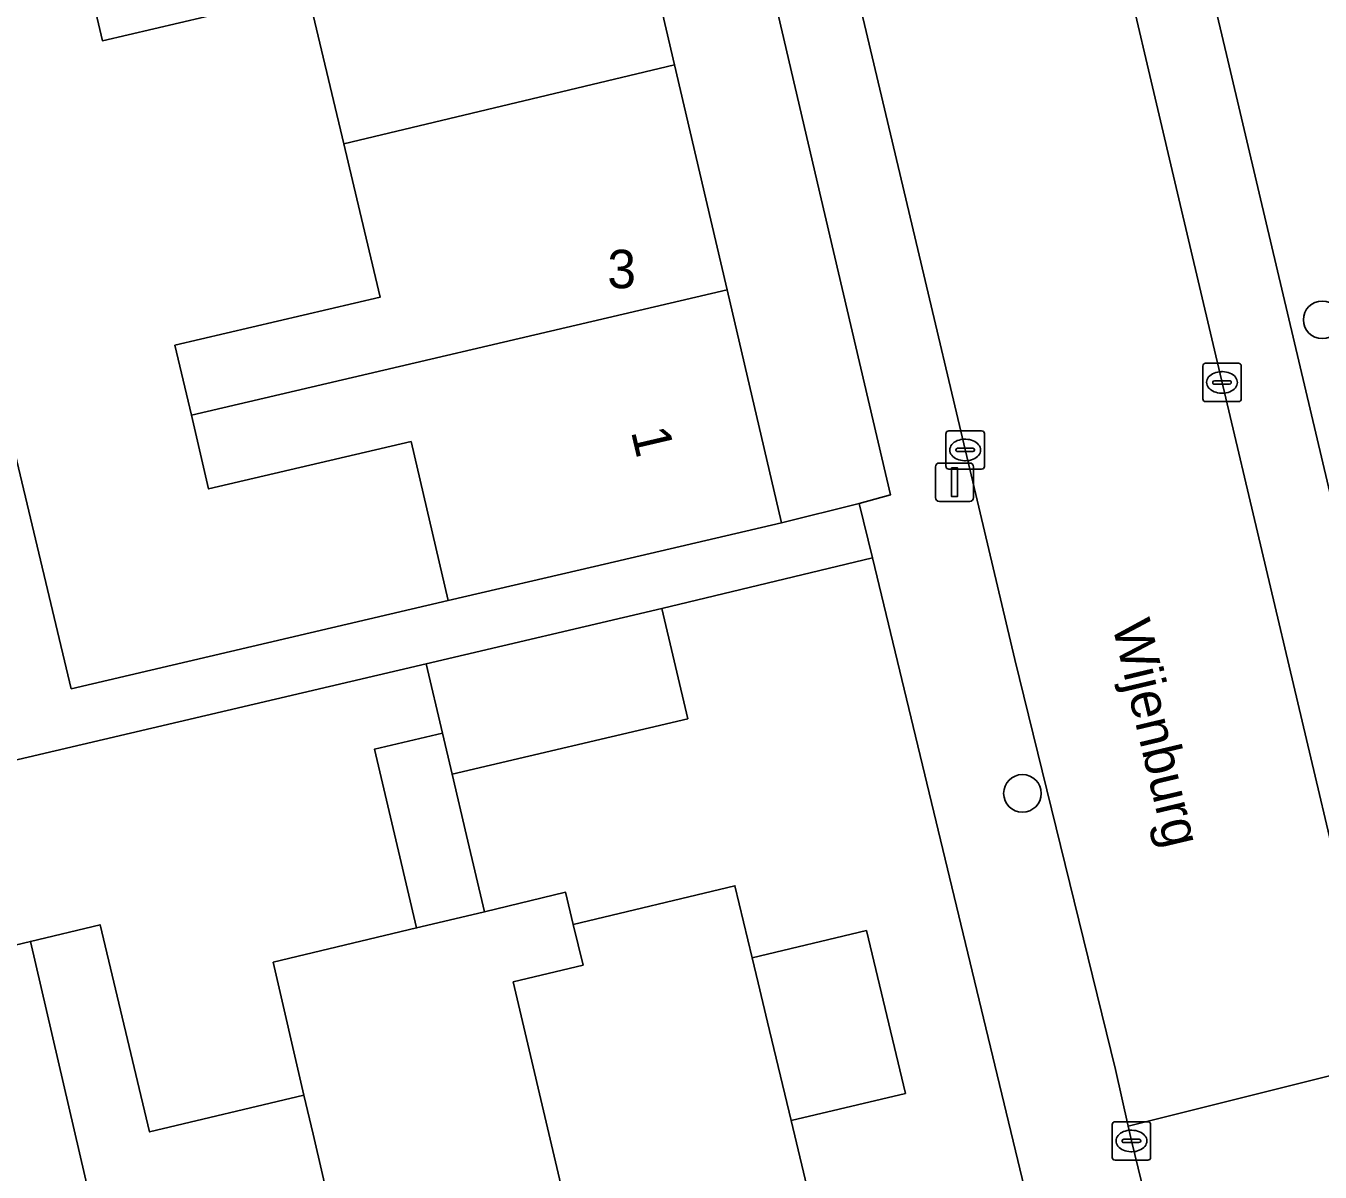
# Model space of a CAD drawing. Extents: x 158031 to 159244, y 380104 to 381214.
# Drawn here: x 158590.29 to 158623.97, y 380724.66 to 380754.5 of the extents above; entities that cross this region are included whole.
import ezdxf

# ---------------------------------------------------------------- set-up
doc = ezdxf.new("R2010")
doc.units = 0
for name, color, linetype in [('IMGEO_Boom', 7, 'Continuous'), ('IMGEO_Erf', 7, 'Continuous'), ('IMGEO_Kolk', 7, 'Continuous'), ('IMGEO_Lichtmast', 7, 'Continuous'), ('IMGEO_Openbare_ruimte_label', 7, 'Continuous'), ('IMGEO_Pand', 7, 'Continuous'), ('IMGEO_Pand_nummerreeks', 7, 'Continuous'), ('IMGEO_Parkeervlak_open', 7, 'Continuous'), ('IMGEO_Rijbaan_lokaal_gesloten', 7, 'Continuous'), ('IMGEO_Rijbaan_lokaal_open', 7, 'Continuous'), ('IMGEO_Voetpad_open', 7, 'Continuous')]:
    doc.layers.add(name, color=color, linetype=linetype)

msp = doc.modelspace()

# ---------------------------------------------------------------- linework, layer by layer
at = {"layer": 'IMGEO_Boom'}
for centre in [(158624.026, 380746.851), (158616.223, 380734.523)]:
    msp.add_circle(centre, 0.489, dxfattribs=at)
at = {"layer": 'IMGEO_Erf'}
for points in [[(158604.491, 380777.798), (158597.408, 380776.13), (158598.809, 380770.25), (158603.015, 380771.233), (158604.431, 380765.183), (158605.801, 380759.324), (158607.166, 380753.49), (158607.983, 380750), (158608.538, 380747.627), (158609.955, 380741.569), (158611.977, 380742.07), (158612.789, 380742.296), (158610.988, 380750)], [(158598.899, 380750), (158598.561, 380751.427), (158597.627, 380755.367), (158592.275, 380754.116), (158591.833, 380756.006), (158591.411, 380757.814), (158596.728, 380759.056), (158595.788, 380763.076), (158594.324, 380762.734), (158593.901, 380764.544), (158592.892, 380768.863), (158590.165, 380768.213), (158587.286, 380767.526), (158584.406, 380766.84), (158586.112, 380759.687), (158591.465, 380737.246), (158601.276, 380739.54), (158600.309, 380743.68), (158595.041, 380742.448), (158594.593, 380744.364), (158594.166, 380746.188), (158599.506, 380747.436)]]:
    msp.add_lwpolyline(points, close=True, dxfattribs=at)
for points in [[(158617.16, 380720.572), (158612.318, 380740.656), (158606.84, 380739.335), (158607.513, 380736.466), (158601.378, 380735.027), (158601.753, 380733.429), (158602.218, 380731.442), (158604.333, 380731.948), (158604.533, 380731.113), (158608.741, 380732.119), (158609.189, 380730.243), (158612.163, 380730.953), (158613.176, 380726.715), (158610.202, 380726.004), (158611.444, 380720.808)], [(158588.547, 380730.227), (158590.405, 380730.671), (158592.215, 380731.104), (158593.505, 380725.71), (158597.522, 380726.67), (158596.722, 380730.128), (158600.454, 380731.021), (158599.987, 380733.015), (158599.363, 380735.675), (158601.129, 380736.089), (158600.705, 380737.896), (158568.508, 380730.343), (158573.761, 380708.16), (158615.556, 380718.152)]]:
    msp.add_lwpolyline(points, dxfattribs=at)
at = {"layer": 'IMGEO_Kolk'}
for p, q in [((158620.917, 380744.795), (158620.917, 380745.647)), ((158620.992, 380745.721), (158621.844, 380745.721)), ((158621.405, 380745.501), (158621.43, 380745.501)), ((158621.918, 380745.647), (158621.918, 380744.795)), ((158621.176, 380745.215), (158621.176, 380745.227)), ((158621.614, 380745.178), (158621.216, 380745.178)), ((158621.219, 380745.264), (158621.617, 380745.264)), ((158621.66, 380745.227), (158621.66, 380745.215)), ((158621.428, 380744.941), (158621.403, 380744.941)), ((158621.844, 380744.721), (158620.992, 380744.721)), ((158614.233, 380743.036), (158614.233, 380743.888)), ((158614.308, 380743.962), (158615.16, 380743.962)), ((158615.234, 380743.888), (158615.234, 380743.036)), ((158614.535, 380743.505), (158614.933, 380743.505)), ((158614.721, 380743.742), (158614.746, 380743.742)), ((158614.492, 380743.456), (158614.492, 380743.468)), ((158614.93, 380743.419), (158614.532, 380743.419)), ((158614.744, 380743.182), (158614.719, 380743.182)), ((158614.976, 380743.468), (158614.976, 380743.456)), ((158615.16, 380742.962), (158614.308, 380742.962)), ((158618.634, 380725.975), (158619.486, 380725.975)), ((158618.559, 380725.049), (158618.559, 380725.901)), ((158619.047, 380725.755), (158619.072, 380725.755)), ((158619.56, 380725.901), (158619.56, 380725.049)), ((158618.818, 380725.469), (158618.818, 380725.481)), ((158619.256, 380725.432), (158618.858, 380725.432)), ((158618.861, 380725.518), (158619.259, 380725.518)), ((158619.302, 380725.481), (158619.302, 380725.469)), ((158619.486, 380724.975), (158618.634, 380724.975)), ((158619.07, 380725.195), (158619.045, 380725.195))]:
    msp.add_line(p, q, dxfattribs=at)
for points in [[(158620.917, 380744.795), (158620.917, 380745.647)], [(158620.992, 380745.721), (158621.844, 380745.721)], [(158621.918, 380745.647), (158621.918, 380744.795)], [(158621.844, 380744.721), (158620.992, 380744.721)], [(158614.233, 380743.036), (158614.233, 380743.888)], [(158614.308, 380743.962), (158615.16, 380743.962)], [(158615.234, 380743.888), (158615.234, 380743.036)], [(158615.16, 380742.962), (158614.308, 380742.962)], [(158618.634, 380725.975), (158619.486, 380725.975)], [(158618.559, 380725.049), (158618.559, 380725.901)], [(158619.56, 380725.901), (158619.56, 380725.049)], [(158619.486, 380724.975), (158618.634, 380724.975)]]:
    msp.add_lwpolyline(points, dxfattribs=at)
for centre, radius, start, end in [((158620.994, 380745.645), 0.0765, 91.552, 178.448), ((158620.994, 380745.645), 0.0765, 91.552, 178.448), ((158621.842, 380745.645), 0.0765, 1.552, 88.448), ((158621.842, 380745.645), 0.0765, 1.552, 88.448), ((158621.216, 380745.224), 0.0403, 85.8775, 175.7526), ((158621.213, 380745.214), 0.0366, 178.938, 274.7102), ((158621.617, 380745.221), 0.043, 264.8664, 352.4533), ((158621.621, 380745.226), 0.0386, 1.7309, 96.639), ((158620.994, 380744.797), 0.0765, 181.552, 268.448), ((158620.994, 380744.797), 0.0765, 181.552, 268.448), ((158621.842, 380744.797), 0.0765, 271.552, 358.448), ((158621.842, 380744.797), 0.0765, 271.552, 358.448), ((158614.31, 380743.886), 0.0765, 91.552, 178.448), ((158614.31, 380743.886), 0.0765, 91.552, 178.448), ((158615.158, 380743.886), 0.0765, 1.552, 88.448), ((158615.158, 380743.886), 0.0765, 1.552, 88.448), ((158614.532, 380743.465), 0.0403, 85.8775, 175.7526), ((158614.937, 380743.467), 0.0386, 1.7309, 96.639), ((158614.529, 380743.455), 0.0366, 178.938, 274.7102), ((158614.933, 380743.462), 0.043, 264.8664, 352.4533), ((158614.31, 380743.038), 0.0765, 181.552, 268.448), ((158614.31, 380743.038), 0.0765, 181.552, 268.448), ((158615.158, 380743.038), 0.0765, 271.552, 358.448), ((158615.158, 380743.038), 0.0765, 271.552, 358.448), ((158618.636, 380725.899), 0.0765, 91.552, 178.448), ((158618.636, 380725.899), 0.0765, 91.552, 178.448), ((158619.484, 380725.899), 0.0765, 1.552, 88.448), ((158619.484, 380725.899), 0.0765, 1.552, 88.448), ((158618.858, 380725.478), 0.0403, 85.8775, 175.7526), ((158618.855, 380725.468), 0.0366, 178.938, 274.7102), ((158619.259, 380725.475), 0.043, 264.8664, 352.4533), ((158619.263, 380725.48), 0.0386, 1.7309, 96.639), ((158618.636, 380725.051), 0.0765, 181.552, 268.448), ((158618.636, 380725.051), 0.0765, 181.552, 268.448), ((158619.484, 380725.051), 0.0765, 271.552, 358.448), ((158619.484, 380725.051), 0.0765, 271.552, 358.448)]:
    msp.add_arc(centre, radius, start, end, dxfattribs=at)
for centre, major_axis, ratio, start_param, end_param in [((158621.404, 380745.221), (-0.387, 0.002), 0.722429, 4.712389, 7.853982), ((158621.429, 380745.221), (-0.39, 0.002), 0.717154, 1.570796, 4.712389), ((158614.72, 380743.462), (-0.387, 0.002), 0.722429, 4.712389, 7.853982), ((158614.745, 380743.462), (-0.39, 0.002), 0.717154, 1.570796, 4.712389), ((158619.046, 380725.475), (-0.387, 0.002), 0.722429, 4.712389, 7.853982), ((158619.071, 380725.475), (-0.39, 0.002), 0.717154, 1.570796, 4.712389)]:
    msp.add_ellipse(centre, major_axis=major_axis, ratio=ratio, start_param=start_param, end_param=end_param, dxfattribs=at)
at = {"layer": 'IMGEO_Lichtmast'}
for p, q in [((158613.96, 380742.223), (158613.96, 380743.023)), ((158613.96, 380743.023), (158613.96, 380742.223)), ((158614.06, 380743.123), (158614.85, 380743.123)), ((158614.85, 380743.123), (158614.06, 380743.123)), ((158614.95, 380743.023), (158614.95, 380742.223)), ((158614.95, 380742.223), (158614.95, 380743.023)), ((158614.85, 380742.123), (158614.06, 380742.123)), ((158614.06, 380742.123), (158614.85, 380742.123))]:
    msp.add_line(p, q, dxfattribs=at)
msp.add_lwpolyline([(158614.38, 380742.998), (158614.53, 380742.998), (158614.53, 380742.248), (158614.38, 380742.248), (158614.38, 380742.998)], dxfattribs=at)
for centre, start, end in [((158614.06, 380743.023), 90, 180), ((158614.06, 380743.023), 90, 180), ((158614.85, 380743.023), 0, 90), ((158614.85, 380743.023), 360, 90), ((158614.06, 380742.223), 180, 270), ((158614.06, 380742.223), 180, 270), ((158614.85, 380742.223), 270, 0), ((158614.85, 380742.223), 270, 0)]:
    msp.add_arc(centre, 0.1, start, end, dxfattribs=at)
at = {"layer": 'IMGEO_Pand'}
for points in [[(158598.561, 380751.427), (158607.166, 380753.49), (158605.801, 380759.324), (158591.833, 380756.006), (158592.275, 380754.116), (158597.627, 380755.367)], [(158598.561, 380751.427), (158598.899, 380750), (158599.506, 380747.436), (158594.166, 380746.188), (158594.593, 380744.364), (158608.538, 380747.627), (158607.983, 380750), (158607.166, 380753.49)], [(158608.538, 380747.627), (158594.593, 380744.364), (158595.041, 380742.448), (158600.309, 380743.68), (158601.276, 380739.54), (158605.087, 380740.431), (158609.955, 380741.569)], [(158606.84, 380739.335), (158600.705, 380737.896), (158601.129, 380736.089), (158601.378, 380735.027), (158607.513, 380736.466)], [(158601.378, 380735.027), (158601.129, 380736.089), (158599.363, 380735.675), (158599.987, 380733.015), (158600.454, 380731.021), (158600.711, 380731.082), (158602.218, 380731.442), (158601.753, 380733.429)], [(158609.189, 380730.243), (158608.741, 380732.119), (158604.533, 380731.113), (158604.786, 380730.053), (158602.972, 380729.617), (158605.379, 380719.358), (158611.444, 380720.808), (158610.202, 380726.004), (158609.589, 380728.57), (158609.345, 380729.59)], [(158602.972, 380729.617), (158604.786, 380730.053), (158604.533, 380731.113), (158604.333, 380731.948), (158602.218, 380731.442), (158600.711, 380731.082), (158600.454, 380731.021), (158596.722, 380730.128), (158597.522, 380726.67), (158597.758, 380725.65), (158599.537, 380717.961), (158605.379, 380719.358)], [(158597.522, 380726.67), (158593.505, 380725.71), (158592.215, 380731.104), (158590.405, 380730.671), (158593.675, 380716.56), (158599.537, 380717.961), (158597.758, 380725.65)], [(158609.189, 380730.243), (158609.345, 380729.59), (158609.589, 380728.57), (158610.202, 380726.004), (158613.176, 380726.715), (158612.163, 380730.953)], [(158590.405, 380730.671), (158588.547, 380730.227), (158589.833, 380724.846), (158585.83, 380723.889), (158587.833, 380715.163), (158593.675, 380716.56)]]:
    msp.add_lwpolyline(points, close=True, dxfattribs=at)
at = {"layer": 'IMGEO_Parkeervlak_open'}
msp.add_lwpolyline([(158627.774, 380727.324), (158622.417, 380750), (158621.53, 380753.756), (158620.656, 380757.457), (158615.415, 380779.644), (158613.34, 380779.174), (158616.461, 380766.319), (158620.294, 380750), (158621.401, 380745.287), (158625.599, 380727.516)], dxfattribs=at)
at = {"layer": 'IMGEO_Rijbaan_lokaal_gesloten'}
msp.add_lwpolyline([(158625.847, 380726.467), (158625.599, 380727.516), (158618.975, 380725.857), (158619.06, 380725.475), (158620.191, 380720.852), (158626.931, 380722.326), (158626.597, 380723.434)], close=True, dxfattribs=at)
at = {"layer": 'IMGEO_Rijbaan_lokaal_open'}
msp.add_lwpolyline([(158601.755, 380798.591), (158602.585, 380794.954), (158604.015, 380788.692), (158605.732, 380781.448), (158613.185, 380750), (158615.123, 380741.822), (158616.028, 380738.005), (158618.646, 380727.333), (158618.975, 380725.857), (158625.599, 380727.516), (158621.401, 380745.287), (158620.294, 380750), (158616.461, 380766.319), (158613.34, 380779.174), (158612.554, 380782.409), (158609.13, 380797.277)], dxfattribs=at)
at = {"layer": 'IMGEO_Voetpad_open'}
for points in [[(158582.927, 380865.443), (158599.515, 380795.166), (158600.252, 380792.284), (158601.053, 380788.365), (158601.167, 380787.602), (158602.537, 380781.61), (158604.491, 380777.798), (158610.988, 380750), (158612.789, 380742.296), (158611.977, 380742.07), (158612.318, 380740.656), (158617.16, 380720.572)], [(158609.13, 380797.277), (158612.554, 380782.409), (158613.34, 380779.174), (158615.415, 380779.644), (158620.656, 380757.457), (158621.53, 380753.756), (158622.417, 380750), (158627.774, 380727.324)], [(158620.191, 380720.852), (158619.06, 380725.475), (158618.975, 380725.857), (158618.646, 380727.333), (158616.028, 380738.005), (158615.123, 380741.822), (158613.185, 380750), (158605.732, 380781.448), (158604.015, 380788.692)]]:
    msp.add_lwpolyline(points, dxfattribs=at)
msp.add_lwpolyline([(158600.705, 380737.896), (158606.84, 380739.335), (158612.318, 380740.656), (158611.977, 380742.07), (158609.955, 380741.569), (158605.087, 380740.431), (158601.276, 380739.54), (158591.465, 380737.246), (158586.112, 380759.687), (158584.406, 380766.84), (158583.009, 380772.697), (158581.455, 380772.326), (158582.853, 380766.459), (158588.426, 380742.845), (158588.845, 380741.072), (158589.846, 380736.837), (158579.907, 380734.482), (158576.02, 380733.561), (158571.154, 380732.409), (158568.185, 380731.708), (158568.508, 380730.343)], close=True, dxfattribs=at)

# ---------------------------------------------------------------- texts
at = {"layer": 'IMGEO_Openbare_ruimte_label'}
msp.add_text('Wijenburg', height=1, rotation=283.3553, dxfattribs=at).set_placement((158618.553, 380738.911))
at = {"layer": 'IMGEO_Pand_nummerreeks'}
msp.add_text('3', height=1, dxfattribs=at).set_placement((158605.42, 380747.673))
msp.add_text('1', height=1, rotation=283.1677, dxfattribs=at).set_placement((158606.03, 380743.946))

doc.saveas('drawing.dxf')
